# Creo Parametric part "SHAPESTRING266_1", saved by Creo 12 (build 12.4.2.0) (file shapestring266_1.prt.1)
Units: Custom; MM, KILOGRAM, SECS

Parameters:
  PTC_WM_ITERATION = "0"
  PTC_WM_VERSION = "-.0"
  PTC_WM_LIFECYCLE_STATE = "In Work"
  PTC_WM_LIFECYCLE = "MO_CADDocument"
  PTC_WM_CREATED_BY = "Maximilian Roepper (Z0017RMS: MO)"
  PTC_WM_CREATED_ON = "18-Sep-26 11:36:42 AM"
  PTC_WM_MODIFIED_BY = "Maximilian Roepper (Z0017RMS: MO)"
  PTC_WM_MODIFIED_ON = "18-Sep-26 11:36:46 AM"
  PDMLINKNUMBER = "PDM000071454853"
  PTC_WM_NAME = "shapestring266_1.prt"
  PTC_WM_NUMBER = "PDM000071454853"

Other parameters: WEIGHT, WEIGHT_FACTOR, WEIGHT_ADD, _MASS_TEMP, _DIFF_TEMP, MC_ERRORS, SUPPLIER

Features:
  1. coordinate system
  2. datum plane "PRT_YZ"
  3. datum plane "PRT_XY"
  4. datum plane "PRT_XZ"
  5. coordinate system
  6. datum axis
  7. datum axis
  8. datum axis
  9. coordinate system
  10. imported feature
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
Other named items: PRT, SIEMENS_MO, DRW_VIEW_ORG, PRT_X, PRT_Y, PRT_Z, CS0, ROUGH_GROB

Layers: 00_STD_CSYS-KSYS, 01_STD_PLANES-EBENEN, 02_STD_AXES-ACHSEN, 03_STD_CSYS-KSYS, 24_IMPORT_FEAT-IMPORT_KE, WHITE

Surfaces: 1 plane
